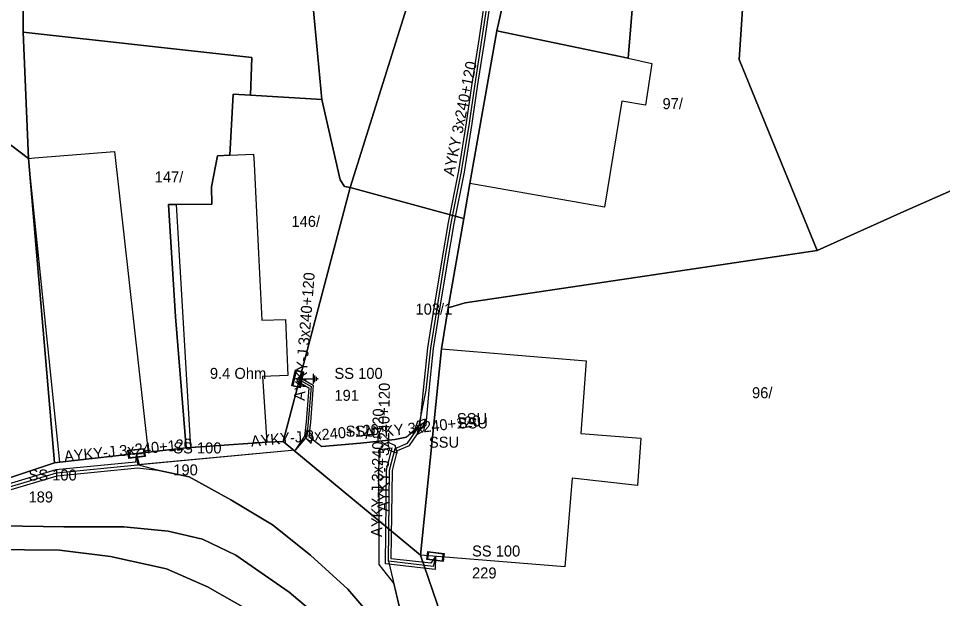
# Model space of a CAD drawing. Extents: x -793400 to -756198, y -1074141 to -1042963.
# Drawn here: x -783501.9 to -783438.8, y -1065252.1 to -1065212.5 of the extents above; entities that cross this region are included whole.
import ezdxf

# ---------------------------------------------------------------- set-up
doc = ezdxf.new("R2010")
doc.units = 0
for name, color, linetype in [('Parcela', 7, 'Continuous'), ('Popiskový text - Parcela', 7, 'Continuous'), ('Popiskový text - Přípojková skříň nn - SJZ', 7, 'Continuous'), ('Popiskový text - Přípojková skříň nn - Typ', 7, 'Continuous'), ('Popiskový text - Spojka nn - Typ', 7, 'Continuous'), ('Popiskový text - Uzemnění - Odpor', 7, 'Continuous'), ('Popiskový text - Vedení nn kabelové', 7, 'Continuous'), ('Skříň', 7, 'Continuous'), ('Spojka nn', 7, 'Continuous'), ('Spojnice nn', 7, 'Continuous'), ('Stavební objekt', 7, 'Continuous'), ('Uzemnění', 7, 'Continuous'), ('Vedení nn kabelové', 7, 'Continuous')]:
    doc.layers.add(name, color=color, linetype=linetype)

msp = doc.modelspace()

# ---------------------------------------------------------------- linework, layer by layer
at = {"layer": 'Parcela'}
for points in [[(-783481.96, -1065210.01), (-783481.2, -1065218.06), (-783486.07, -1065217.76), (-783485.98, -1065215.18), (-783501.19, -1065213.49), (-783501.6, -1065213.45), (-783501.59, -1065189.62), (-783502.22, -1065183.11), (-783506.07, -1065167.92), (-783485.73, -1065163.03), (-783483, -1065162.45), (-783470.12, -1065156.38), (-783468.61, -1065165.85), (-783468.3, -1065170.76), (-783474.5, -1065171.05), (-783475.22, -1065181.77), (-783475.86, -1065189.4), (-783483.42, -1065209.48), (-783483.12, -1065209.63)], [(-783501.59, -1065189.62), (-783501.6, -1065213.45), (-783501.23, -1065222.08), (-783513.38, -1065212.87), (-783518.32, -1065213.36), (-783521.92, -1065183.59), (-783523.84, -1065172.2), (-783506.34, -1065166.89), (-783506.07, -1065167.92), (-783502.22, -1065183.11)], [(-783416.03, -1065186.09), (-783403.39, -1065195.23), (-783407.54, -1065201.94), (-783409.86, -1065205.07), (-783416.28, -1065212.21), (-783421, -1065216.11), (-783424.16, -1065218.04), (-783438.03, -1065224.17), (-783441.5, -1065225.71), (-783447.41, -1065228.37), (-783452.73, -1065215.33), (-783452.34, -1065209.47), (-783459.78, -1065208.85), (-783460.26, -1065214.69), (-783460.3, -1065215.24), (-783468.73, -1065213.48), (-783469.27, -1065213.37), (-783464.68, -1065192.93), (-783464.13, -1065193.03), (-783454.3, -1065194.92), (-783453.6, -1065190.73), (-783449.1, -1065190.18)], [(-783475.55, -1065212.17), (-783479.28, -1065224.06), (-783479.67, -1065223.99), (-783479.97, -1065223.54), (-783481.2, -1065218.06), (-783481.96, -1065210.01), (-783483.12, -1065209.63), (-783480.3, -1065201.56), (-783472.68, -1065203.99)], [(-783452.34, -1065209.47), (-783452.73, -1065215.33), (-783447.41, -1065228.37), (-783471.42, -1065231.93), (-783472.58, -1065232.29), (-783471.52, -1065226.18), (-783471.1, -1065223.78), (-783469.27, -1065213.37), (-783468.73, -1065213.48), (-783460.3, -1065215.24), (-783460.26, -1065214.69), (-783459.78, -1065208.85)], [(-783502.93, -1065244.02), (-783517.47, -1065244.61), (-783518.03, -1065233.96), (-783518.04, -1065233.82), (-783517.75, -1065232.21), (-783517.7, -1065229.65), (-783517.59, -1065227.08), (-783517.76, -1065223.95), (-783517.93, -1065220.91), (-783518.32, -1065213.36), (-783513.38, -1065212.87), (-783501.23, -1065222.08), (-783499.45, -1065242.86)], [(-783485.98, -1065215.18), (-783486.07, -1065217.76), (-783487.27, -1065217.69), (-783487.49, -1065221.86), (-783488.33, -1065221.91), (-783488.73, -1065224.01), (-783488.71, -1065225.2), (-783491.14, -1065225.22), (-783491.67, -1065225.23), (-783491.19, -1065232.89), (-783490.48, -1065241.84), (-783493.07, -1065242.13), (-783499.1, -1065242.82), (-783499.45, -1065242.86), (-783501.23, -1065222.08), (-783501.6, -1065213.45), (-783501.19, -1065213.49)], [(-783490.15, -1065241.81), (-783490.48, -1065241.84), (-783491.19, -1065232.89), (-783491.67, -1065225.23), (-783491.14, -1065225.22), (-783488.71, -1065225.2), (-783488.73, -1065224.01), (-783488.33, -1065221.91), (-783487.49, -1065221.86), (-783487.27, -1065217.69), (-783486.07, -1065217.76), (-783481.2, -1065218.06), (-783479.97, -1065223.54), (-783479.67, -1065223.99), (-783479.28, -1065224.06), (-783483.86, -1065241.4), (-783484.97, -1065241.46)], [(-783473.04, -1065235.09), (-783474.48, -1065249.17), (-783483.86, -1065241.4), (-783479.28, -1065224.06), (-783471.52, -1065226.18), (-783472.58, -1065232.29)], [(-783436.45, -1065250.48), (-783436.59, -1065253.58), (-783444.3, -1065253.99), (-783455.9, -1065253.3), (-783460.81, -1065253.03), (-783461.03, -1065253.4), (-783461.1, -1065254.06), (-783473.08, -1065253.23), (-783474.48, -1065249.17), (-783473.04, -1065235.09), (-783472.58, -1065232.29), (-783471.42, -1065231.93), (-783447.41, -1065228.37), (-783441.5, -1065225.71), (-783438.03, -1065224.17), (-783436.74, -1065242.46), (-783436.65, -1065245.81), (-783436.26, -1065245.82)]]:
    msp.add_lwpolyline(points, close=True, dxfattribs=at)
for points in [[(-783462.64, -1065176.13), (-783462.8, -1065182.31), (-783464.58, -1065192.39), (-783464.68, -1065192.93), (-783469.27, -1065213.37), (-783471.1, -1065223.78), (-783471.52, -1065226.18), (-783479.28, -1065224.06), (-783475.55, -1065212.17), (-783472.68, -1065203.99), (-783468.27, -1065186.66), (-783467.95, -1065176.22)], [(-783540.31, -1065245.49), (-783533.99, -1065245.21), (-783533.56, -1065245.4), (-783526.99, -1065244.99), (-783525.42, -1065244.93), (-783517.47, -1065244.61), (-783502.93, -1065244.02), (-783499.45, -1065242.86), (-783499.1, -1065242.82), (-783493.07, -1065242.13), (-783490.48, -1065241.84), (-783490.15, -1065241.81), (-783484.97, -1065241.46), (-783483.86, -1065241.4), (-783474.48, -1065249.17), (-783473.08, -1065253.23)], [(-783486.18, -1065252.95), (-783489.01, -1065251.32), (-783491.82, -1065250.1), (-783495.64, -1065249.27), (-783499.12, -1065248.83), (-783556.41, -1065248.29), (-783589.66, -1065247.24), (-783601.8, -1065247.03), (-783608.78, -1065247.15), (-783617.15, -1065247.78), (-783626.46, -1065248.97), (-783645.69, -1065252.29)], [(-783645.69, -1065252.29), (-783626.46, -1065248.97), (-783617.15, -1065247.78), (-783608.78, -1065247.15), (-783601.8, -1065247.03), (-783589.66, -1065247.24), (-783556.41, -1065248.29), (-783499.12, -1065248.83), (-783495.64, -1065249.27), (-783491.82, -1065250.1), (-783489.01, -1065251.32), (-783486.18, -1065252.95)]]:
    msp.add_lwpolyline(points, dxfattribs=at)
at = {"layer": 'Skříň'}
for points in [[(-783483.247, -1065237.617), (-783483.001, -1065236.52), (-783482.452, -1065236.643), (-783482.699, -1065237.74)], [(-783482.959, -1065236.587), (-783483.18, -1065237.575), (-783482.741, -1065237.673), (-783482.519, -1065236.685)], [(-783494.441, -1065242.005), (-783493.323, -1065241.876), (-783493.259, -1065242.435), (-783494.376, -1065242.564)], [(-783493.373, -1065241.939), (-783494.379, -1065242.055), (-783494.327, -1065242.502), (-783493.321, -1065242.386)], [(-783473.983, -1065248.91), (-783472.867, -1065249.052), (-783472.937, -1065249.61), (-783474.053, -1065249.468)], [(-783472.929, -1065249.101), (-783473.934, -1065248.973), (-783473.991, -1065249.42), (-783472.986, -1065249.547)]]:
    msp.add_lwpolyline(points, close=True, dxfattribs=at)
at = {"layer": 'Spojka nn'}
for points in [[(-783474.861, -1065240.566), (-783474.328, -1065240.402), (-783474.136, -1065239.878), (-783474.672, -1065240.039)], [(-783474.17, -1065240.091), (-783474.646, -1065240.381), (-783474.704, -1065240.936), (-783474.224, -1065240.648)], [(-783481.934, -1065241.55), (-783481.854, -1065240.998), (-783482.245, -1065240.599), (-783482.329, -1065241.153)], [(-783476.079, -1065242.21), (-783476.214, -1065241.669), (-783476.727, -1065241.449), (-783476.595, -1065241.993)]]:
    msp.add_lwpolyline(points, close=True, dxfattribs=at)
at = {"layer": 'Spojnice nn'}
msp.add_line((-783493.85, -1065242.22), (-783493.8, -1065243.01), dxfattribs=at)
for points in [[(-783474.6, -1065240.4), (-783474.08, -1065237.9), (-783473.78, -1065235.03), (-783473.39, -1065232.61), (-783472.81, -1065229.03), (-783472.38, -1065226.49), (-783471.67, -1065222.97), (-783471.14, -1065219.67), (-783470.78, -1065217.14), (-783470.26, -1065213.84), (-783469.73, -1065210.24), (-783469.15, -1065206.56)], [(-783482.85, -1065237.13), (-783481.95, -1065237.65), (-783482.14, -1065240.07), (-783482.24, -1065241.06)], [(-783474.6, -1065240.4), (-783475.44, -1065241.12), (-783476.24, -1065241.26), (-783478.58, -1065241.52), (-783481.2, -1065241.74)], [(-783476.21, -1065241.88), (-783475.37, -1065241.51), (-783474.6, -1065240.4)], [(-783482.24, -1065241.06), (-783483.04, -1065241.99), (-783493.8, -1065243.01)], [(-783476.67, -1065249.59), (-783476.59, -1065243.36), (-783476.21, -1065241.88)], [(-783502.82, -1065244.6), (-783499.32, -1065243.55), (-783493.8, -1065243.01)], [(-783476.67, -1065249.59), (-783475.72, -1065253.51), (-783475.77, -1065254.5), (-783476.49, -1065254.72), (-783477.11, -1065254.2), (-783479.44, -1065251.48), (-783481.98, -1065249.16), (-783484.57, -1065247.1), (-783487.42, -1065245.39), (-783490.27, -1065243.82), (-783492.43, -1065243.36), (-783493.8, -1065243.01)], [(-783515.66, -1065245.16), (-783515.87, -1065246.15), (-783515.91, -1065246.79), (-783515.27, -1065247.09), (-783513.48, -1065247.15), (-783509.72, -1065247.2), (-783506.53, -1065247.14), (-783503.04, -1065247.17), (-783498.83, -1065247.24), (-783494.73, -1065247.24), (-783491.7, -1065247.52), (-783489.36, -1065248.08), (-783487.08, -1065249.17), (-783485.45, -1065250.3), (-783483.44, -1065251.7), (-783480.81, -1065253.93), (-783479.82, -1065254.73), (-783478.85, -1065255.89), (-783477.73, -1065257.7), (-783476.81, -1065260.33), (-783476.02, -1065263.52), (-783474.95, -1065266.48), (-783474.45, -1065269.09), (-783474.22, -1065273.81)], [(-783473.46, -1065249.26), (-783473.62, -1065249.94), (-783476.67, -1065249.59)]]:
    msp.add_lwpolyline(points, dxfattribs=at)
at = {"layer": 'Stavební objekt'}
for points in [[(-783458.68, -1065215.59), (-783459.13, -1065218.44), (-783460.74, -1065218.17), (-783461.93, -1065225.41), (-783471.1, -1065223.78), (-783469.27, -1065213.37), (-783468.73, -1065213.48), (-783460.3, -1065215.24)], [(-783493.07, -1065242.13), (-783499.1, -1065242.82), (-783501.23, -1065222.08), (-783500.83, -1065222.04), (-783495.35, -1065221.61)], [(-783485.53, -1065228.56), (-783485.3, -1065233.13), (-783483.7, -1065233.08), (-783483.54, -1065236.9), (-783485.27, -1065236.97), (-783484.97, -1065241.46), (-783490.15, -1065241.81), (-783491.14, -1065225.22), (-783488.71, -1065225.2), (-783488.73, -1065224.01), (-783488.33, -1065221.91), (-783487.49, -1065221.86), (-783485.88, -1065221.78), (-783485.84, -1065222.44)], [(-783459.43, -1065241.17), (-783459.66, -1065244.41), (-783464.13, -1065243.9), (-783464.63, -1065249.97), (-783474.48, -1065249.17), (-783473.04, -1065235.09), (-783463.16, -1065235.9), (-783463.54, -1065240.85)]]:
    msp.add_lwpolyline(points, close=True, dxfattribs=at)
at = {"layer": 'Uzemnění'}
for p, q in [((-783481.771, -1065237.475), (-783481.771, -1065236.784)), ((-783481.679, -1065237.35), (-783481.679, -1065236.909)), ((-783481.58, -1065237.274), (-783481.58, -1065236.989)), ((-783481.473, -1065237.182), (-783481.473, -1065237.082)), ((-783482.456, -1065237.13), (-783481.771, -1065237.13))]:
    msp.add_line(p, q, dxfattribs=at)
at = {"layer": 'Vedení nn kabelové'}
for points in [[(-783474.436, -1065240.514), (-783474.101, -1065240.259), (-783473.881, -1065237.92), (-783473.582, -1065235.056), (-783473.193, -1065232.642), (-783472.613, -1065229.063), (-783472.183, -1065226.526), (-783471.473, -1065223.006), (-783470.942, -1065219.7), (-783470.582, -1065217.17), (-783470.062, -1065213.87), (-783469.533, -1065210.274), (-783468.775, -1065206.522), (-783467.905, -1065202.726), (-783466.996, -1065198.95), (-783466.041, -1065195.458), (-783465.252, -1065193.715), (-783464.302, -1065192.745), (-783462.679, -1065191.667), (-783462.362, -1065191.456), (-783455.639, -1065191.456), (-783455.674, -1065189.799), (-783455.671, -1065189.557)], [(-783474.499, -1065240.221), (-783474.279, -1065237.88), (-783473.978, -1065235.004), (-783473.587, -1065232.578), (-783473.007, -1065228.997), (-783472.577, -1065226.454), (-783471.867, -1065222.934), (-783471.338, -1065219.64), (-783470.978, -1065217.11), (-783470.458, -1065213.81), (-783469.927, -1065210.206), (-783469.188, -1065206.554)], [(-783482.85, -1065237.13), (-783482.775, -1065237), (-783481.793, -1065237.567), (-783481.991, -1065240.083), (-783482.091, -1065241.075)], [(-783482.85, -1065237.13), (-783482.925, -1065237.26), (-783482.107, -1065237.733), (-783482.289, -1065240.057), (-783482.389, -1065241.045), (-783483.04, -1065241.99), (-783493.65, -1065243.001), (-783493.85, -1065242.22)], [(-783482.091, -1065241.075), (-783481.2, -1065241.74), (-783478.58, -1065241.52), (-783476.24, -1065241.26), (-783475.44, -1065241.12), (-783474.499, -1065240.221)], [(-783473.46, -1065249.26), (-783473.774, -1065249.721), (-783476.468, -1065249.412), (-783476.39, -1065243.387), (-783476.041, -1065242.024), (-783475.238, -1065241.67), (-783474.436, -1065240.514)], [(-783475.72, -1065253.51), (-783476.302, -1065251.078), (-783477.293, -1065249.796), (-783477.304, -1065246.2), (-783477.319, -1065243.477), (-783477.271, -1065241.955), (-783476.404, -1065241.83)], [(-783473.46, -1065249.26), (-783473.466, -1065250.159), (-783476.872, -1065249.768), (-783476.79, -1065243.333), (-783476.404, -1065241.83)], [(-783493.85, -1065242.22), (-783493.925, -1065242.821), (-783499.359, -1065243.353), (-783502.849, -1065244.4), (-783503.649, -1065244.4), (-783503.73, -1065244.07)], [(-783502.791, -1065244.8), (-783499.281, -1065243.747), (-783493.78, -1065243.209), (-783492.43, -1065243.36), (-783490.27, -1065243.82), (-783487.42, -1065245.39), (-783484.57, -1065247.1), (-783481.98, -1065249.16), (-783479.44, -1065251.48), (-783477.11, -1065254.2)], [(-783480.81, -1065253.93), (-783483.44, -1065251.7), (-783485.45, -1065250.3), (-783487.08, -1065249.17), (-783489.36, -1065248.08), (-783491.7, -1065247.52), (-783494.73, -1065247.24), (-783498.83, -1065247.24), (-783503.04, -1065247.17)]]:
    msp.add_lwpolyline(points, dxfattribs=at)

# ---------------------------------------------------------------- texts
at = {"layer": 'Popiskový text - Parcela'}
for s, p in [('97/', (-783457.961, -1065218.711)), ('147/', (-783492.617, -1065223.715)), ('146/', (-783483.285, -1065226.752)), ('103/1', (-783474.821, -1065232.741)), ('96/', (-783451.85, -1065238.452))]:
    msp.add_text(s, height=0.75, dxfattribs=at).set_placement(p)
at = {"layer": 'Popiskový text - Přípojková skříň nn - SJZ'}
for s, p in [('191', (-783480.35, -1065238.63)), ('190', (-783491.35, -1065243.72)), ('189', (-783501.23, -1065245.57)), ('229', (-783470.96, -1065250.76))]:
    msp.add_text(s, height=0.75, dxfattribs=at).set_placement(p)
at = {"layer": 'Popiskový text - Přípojková skříň nn - Typ'}
for p in [(-783480.35, -1065237.13), (-783491.35, -1065242.22), (-783501.23, -1065244.07), (-783470.96, -1065249.26)]:
    msp.add_text('SS 100', height=0.75, dxfattribs=at).set_placement(p)
at = {"layer": 'Popiskový text - Spojka nn - Typ'}
for p in [(-783471.999, -1065240.221), (-783471.936, -1065240.514), (-783479.591, -1065241.075), (-783473.904, -1065241.83)]:
    msp.add_text('SSU', height=0.75, dxfattribs=at).set_placement(p)
at = {"layer": 'Popiskový text - Uzemnění - Odpor'}
msp.add_text('9.4 Ohm', height=0.75, dxfattribs=at).set_placement((-783488.85, -1065237.13))
at = {"layer": 'Popiskový text - Vedení nn kabelové'}
for s, rotation, p in [('AYKY 3x240+120', 78.60981, (-783472.201, -1065223.324)), ('AYKY-J 3x240+120', 85.4853, (-783482.379, -1065238.643)), ('AYKY-J 3x240+120', 89.26682, (-783476.676, -1065246.185)), ('AYKY 3x240+120', 6.35983, (-783478.246, -1065241.231)), ('AYKY-J 3x240+120', 89.26682, (-783477.099, -1065247.935)), ('AYKY-J 3x240+120', 5.4431, (-783486.023, -1065241.772)), ('AYKY-J 3x240+120', 5.61499, (-783498.77, -1065242.793))]:
    msp.add_text(s, height=0.75, rotation=rotation, dxfattribs=at).set_placement(p)

doc.saveas('drawing.dxf')
